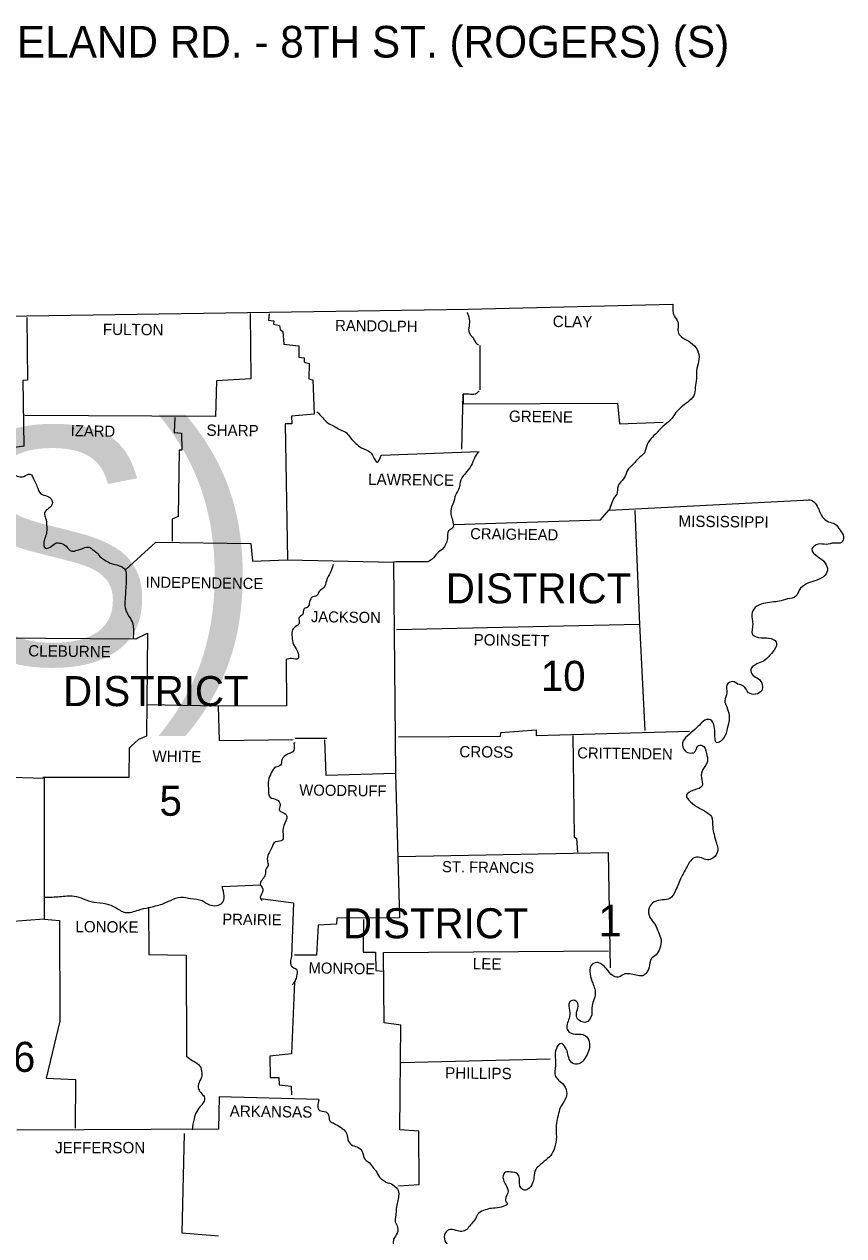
# Model space of a CAD drawing. Extents: x 309389.3 to 309420.2, y 336441.4 to 336461.2.
# Drawn here: x 309416.789 to 309419.827, y 336456.398 to 336460.893 of the extents above; entities that cross this region are included whole.
import ezdxf

# ---------------------------------------------------------------- set-up
doc = ezdxf.new("R2010")
doc.units = 0
doc.layers.add('Level 1', color=7, linetype='Continuous')
doc.layers.add('Level 63', color=7, linetype='Continuous')

msp = doc.modelspace()

# ---------------------------------------------------------------- linework, layer by layer
at = {"layer": 'Level 63'}
for p, q in [((309418.9619, 336459.1024), (309418.9736, 336459.1308)), ((309418.9589, 336459.0907), (309418.9706, 336459.1269)), ((309417.7936, 336458.2441), (309417.91, 336458.2441))]:
    msp.add_line(p, q, dxfattribs=at)
for points in [[(309413.8305, 336459.8092), (309415.4112, 336459.8082), (309416.7984, 336459.8112), (309418.4349, 336459.8366), (309419.1935, 336459.8542)], [(309416.7984, 336459.8053), (309416.8004, 336459.5726), (309416.7838, 336459.5717), (309416.7867, 336459.3282), (309416.7183, 336459.3185), (309416.7241, 336459.253), (309416.7476, 336459.2227), (309416.7457, 336459.1454), (309416.6127, 336459.1406), (309416.6078, 336459.0213), (309416.4866, 336459.0174), (309416.4807, 336458.8727), (309416.4876, 336458.861), (309416.4905, 336458.6302), (309416.6997, 336458.6166), (309416.6968, 336458.1014), (309416.863, 336458.0965), (309416.863, 336457.5725), (309416.732, 336457.5627), (309416.7222, 336457.4474), (309416.5022, 336457.4464)], [(309417.6265, 336459.82), (309417.6284, 336459.5775), (309417.5013, 336459.5707), (309417.4974, 336459.4377), (309416.7906, 336459.4416)], [(309417.6969, 336459.819), (309417.6939, 336459.7955), (309417.7135, 336459.7926), (309417.7125, 336459.7809), (309417.735, 336459.776), (309417.7369, 336459.7603), (309417.7477, 336459.7535), (309417.7506, 336459.7066), (309417.8063, 336459.7007), (309417.8063, 336459.6587), (309417.8269, 336459.6557), (309417.8269, 336459.6391), (309417.8445, 336459.6342), (309417.8435, 336459.5775), (309417.8591, 336459.5746), (309417.863, 336459.4465), (309417.7799, 336459.4387), (309417.7809, 336459.4113), (309417.7555, 336459.4104), (309417.7643, 336458.9059), (309418.1583, 336458.8971), (309418.1651, 336458.1131), (309417.908, 336458.1063), (309417.9031, 336458.2382)], [(309418.4779, 336459.7017), (309418.4779, 336459.5365)], [(309418.4115, 336459.3165), (309418.4164, 336459.5208), (309418.4164, 336459.4847), (309418.9882, 336459.4876), (309418.9961, 336459.4113), (309419.1574, 336459.4172)], [(309417.3469, 336459.4348), (309417.3449, 336459.3781), (309417.3723, 336459.3761), (309417.3733, 336459.3136), (309417.3635, 336459.3136), (309417.3596, 336459.0672), (309417.3371, 336459.0575), (309417.3371, 336458.9753)], [(309418.1123, 336459.295), (309418.475, 336459.3077)], [(309418.9589, 336459.0907), (309419.7009, 336459.1288)], [(309418.3821, 336459.0369), (309418.9247, 336459.0545), (309418.957, 336459.0917)], [(309419.0528, 336459.0897), (309419.0694, 336458.6664), (309419.0889, 336458.2725)], [(309417.165, 336458.8707), (309417.2765, 336458.9714), (309417.6284, 336458.9665), (309417.6353, 336458.901), (309417.7633, 336458.9059)], [(309418.2863, 336458.8991), (309418.1671, 336458.8991), (309418.1583, 336458.8971)], [(309416.6997, 336458.6166), (309417.2022, 336458.6136), (309417.2452, 336458.6342), (309417.2423, 336458.2519), (309417.2129, 336458.2392), (309417.1865, 336458.2167), (309417.1778, 336458.2079), (309417.1768, 336458.0984), (309416.8571, 336458.0984)], [(309419.0694, 336458.6664), (309418.169, 336458.6459)], [(309417.7594, 336458.5364), (309417.7614, 336458.3643), (309417.5072, 336458.3634), (309417.2462, 336458.3683)], [(309417.5072, 336458.3634), (309417.5111, 336458.2353), (309417.7858, 336458.2402)], [(309418.1768, 336458.25), (309418.5542, 336458.2519), (309418.5552, 336458.2656), (309418.6862, 336458.2754), (309418.6862, 336458.2549), (309419.2551, 336458.2705)], [(309418.823, 336458.2549), (309418.8279, 336457.8785), (309418.8367, 336457.8726), (309418.8397, 336457.8218)], [(309418.823, 336458.2549), (309418.8279, 336457.8785), (309418.8367, 336457.8726), (309418.8397, 336457.8218)], [(309418.823, 336458.2549), (309418.8279, 336457.8785), (309418.8367, 336457.8726), (309418.8397, 336457.8218)], [(309418.823, 336458.2549), (309418.8279, 336457.8785), (309418.8367, 336457.8726), (309418.8397, 336457.8218)], [(309418.823, 336458.2549), (309418.8279, 336457.8785), (309418.8367, 336457.8726), (309418.8397, 336457.8218)], [(309417.7936, 336458.2275), (309417.7887, 336458.2265)], [(309418.1651, 336458.1131), (309418.1798, 336457.5774), (309417.9471, 336457.5764), (309417.9461, 336457.5549), (309417.8787, 336457.551), (309417.8728, 336457.4395), (309417.7907, 336457.4395)], [(309418.1768, 336457.8052), (309418.9531, 336457.8208)], [(309418.9531, 336457.8208), (309418.9609, 336457.3926)], [(309418.9531, 336457.8208), (309418.9609, 336457.3926)], [(309418.9531, 336457.8208), (309418.9609, 336457.3926)], [(309418.9531, 336457.8208), (309418.9609, 336457.3926)], [(309418.9531, 336457.8208), (309418.9609, 336457.3926)], [(309418.9531, 336457.8208), (309418.9609, 336457.3926)], [(309418.9531, 336457.8208), (309418.9609, 336457.3926)], [(309418.9531, 336457.8208), (309418.9609, 336457.3926)], [(309417.5228, 336457.6937), (309417.6646, 336457.7006)], [(309417.6646, 336457.6497), (309417.7868, 336457.6341), (309417.7799, 336457.4347)], [(309417.2491, 336457.6175), (309417.2511, 336457.4425), (309417.3889, 336457.4395), (309417.3899, 336457.0642)], [(309416.863, 336457.5725), (309416.9197, 336457.5686), (309416.9206, 336457.1951), (309416.8698, 336456.983), (309416.9783, 336456.9781), (309416.9773, 336456.7982)], [(309418.0468, 336457.5715), (309418.0458, 336457.4503), (309418.0908, 336457.4503), (309418.0928, 336457.3828), (309418.1211, 336457.3799)], [(309418.1768, 336456.5832), (309418.2531, 336456.5881), (309418.2521, 336456.7865), (309418.1808, 336456.7914), (309418.1847, 336457.1795), (309418.1231, 336457.1883), (309418.1211, 336457.4493), (309418.955, 336457.4552)], [(309417.7907, 336457.3408), (309417.779, 336457.0729), (309417.6988, 336457.0642), (309417.7008, 336456.985), (309417.733, 336456.9859), (309417.734, 336456.9586), (309417.778, 336456.9537), (309417.779, 336456.9214)], [(309418.1866, 336457.0417), (309418.738, 336457.0554)], [(309417.8806, 336456.9038), (309417.5111, 336456.9136), (309417.5092, 336456.7934), (309416.7613, 336456.7904)], [(309417.3811, 336456.7777), (309417.3733, 336456.4092), (309417.5092, 336456.3984)]]:
    msp.add_lwpolyline(points, dxfattribs=at)
for points in [[(309419.1935, 336459.8542), (309419.1984, 336459.8112), (309419.2121, 336459.7887), (309419.2141, 336459.7476), (309419.2307, 336459.73), (309419.259, 336459.7124), (309419.2845, 336459.6841), (309419.2903, 336459.6509), (309419.2825, 336459.6166), (309419.2805, 336459.5785), (309419.2766, 336459.5453), (309419.2708, 336459.515), (309419.2473, 336459.4905), (309419.2248, 336459.4729), (309419.2043, 336459.4524), (309419.1896, 336459.4309), (309419.1642, 336459.4074), (309419.1388, 336459.383), (309419.1183, 336459.3615), (309419.0977, 336459.3341), (309419.088, 336459.3038), (309419.0655, 336459.2823), (309419.0479, 336459.2627), (309419.0244, 336459.2364), (309419.0127, 336459.21), (309418.9902, 336459.1797), (309418.9853, 336459.1503), (309418.9706, 336459.1269), (309418.9697, 336459.123)], [(309418.43, 336459.8239), (309418.4388, 336459.7994), (309418.4379, 336459.7731), (309418.4379, 336459.7486), (309418.4506, 336459.732), (309418.4633, 336459.7115), (309418.4731, 336459.7027)], [(309418.474, 336459.5335), (309418.4613, 336459.5208), (309418.4369, 336459.5208), (309418.4164, 336459.5208)], [(309417.8738, 336459.4553), (309417.8953, 336459.4329), (309417.9139, 336459.4143), (309417.9354, 336459.4035), (309417.9608, 336459.3889), (309417.9833, 336459.3771), (309417.9979, 336459.3586), (309418.0185, 336459.338), (309418.039, 336459.3214), (309418.0713, 336459.3058), (309418.082, 336459.2891), (309418.0967, 336459.2686), (309418.1123, 336459.295)], [(309418.4721, 336459.3067), (309418.4574, 336459.2833), (309418.4457, 336459.2559), (309418.4222, 336459.2246), (309418.4046, 336459.1943), (309418.4017, 336459.1738), (309418.388, 336459.1464), (309418.3802, 336459.119), (309418.3714, 336459.0956), (309418.3714, 336459.0711), (309418.3782, 336459.0467), (309418.3763, 336459.0242), (309418.3616, 336459.0135), (309418.3577, 336458.9851), (309418.3518, 336458.9656), (309418.3391, 336458.946), (309418.3206, 336458.9313), (309418.301, 336458.9089), (309418.2863, 336458.8991)], [(309416.7476, 336459.2227), (309416.7867, 336459.2158), (309416.8102, 336459.2246), (309416.8268, 336459.1992), (309416.8356, 336459.1797), (309416.8503, 336459.1513), (309416.8737, 336459.1425), (309416.8913, 336459.1269), (309416.8913, 336459.1102), (309416.8757, 336459.0946), (309416.8639, 336459.079), (309416.8679, 336459.0604), (309416.8718, 336459.035), (309416.8718, 336459.0105), (309416.8659, 336458.988), (309416.861, 336458.9675), (309416.8659, 336458.9499), (309416.8845, 336458.9529), (309416.904, 336458.9675), (309416.9246, 336458.9675), (309416.9441, 336458.9568), (309416.9646, 336458.9382), (309416.9852, 336458.9421), (309417.0018, 336458.947), (309417.0252, 336458.9538), (309417.0419, 336458.945), (309417.0565, 336458.9333), (309417.0741, 336458.9147), (309417.0907, 336458.903), (309417.1123, 336458.8922), (309417.1386, 336458.8854), (309417.1631, 336458.8688), (309417.167, 336458.8404), (309417.166, 336458.816), (309417.1641, 336458.7857), (309417.1621, 336458.7524), (309417.165, 336458.7202), (309417.1758, 336458.6987), (309417.1895, 336458.6733), (309417.1934, 336458.6498), (309417.1924, 336458.6127)], [(309419.6902, 336459.1278), (309419.7009, 336459.1288), (309419.7341, 336459.0936), (309419.7488, 336459.0643), (309419.7703, 336459.0477), (309419.7948, 336459.0389), (309419.8133, 336459.0164), (309419.826, 336458.992), (309419.8192, 336458.9705), (309419.7918, 336458.9685), (309419.7615, 336458.9636), (309419.7322, 336458.9646), (309419.7087, 336458.945), (309419.7302, 336458.9186), (309419.7586, 336458.8942), (309419.7664, 336458.8678), (309419.7508, 336458.8424), (309419.7195, 336458.8287), (309419.6892, 336458.817), (309419.6618, 336458.7935), (309419.6491, 336458.771), (309419.6188, 336458.7612), (309419.5875, 336458.7524), (309419.5601, 336458.7495), (309419.5289, 336458.7436), (309419.4985, 336458.729), (309419.4858, 336458.7036), (309419.4897, 336458.6674), (309419.4888, 336458.6293), (309419.521, 336458.6166), (309419.5494, 336458.6156), (309419.5768, 336458.6009), (309419.5738, 336458.5794), (309419.5533, 336458.552), (309419.5289, 336458.5305), (309419.5044, 336458.5198), (309419.4819, 336458.4993), (309419.4897, 336458.4787), (309419.5103, 336458.465), (309419.5249, 336458.4426), (309419.523, 336458.422), (309419.4995, 336458.4074), (309419.4741, 336458.4132), (309419.4555, 336458.4377), (309419.434, 336458.4455), (309419.4155, 336458.4543), (309419.3939, 336458.4416), (309419.3939, 336458.4132), (309419.3861, 336458.3829), (309419.393, 336458.3604), (309419.4018, 336458.3292), (309419.4008, 336458.3057), (309419.393, 336458.2725), (309419.3763, 336458.2382), (309419.3568, 336458.2275), (309419.349, 336458.2646), (309419.3451, 336458.2949), (309419.3333, 336458.3125), (309419.3177, 336458.3135), (309419.2972, 336458.2988), (309419.2747, 336458.2764), (309419.2463, 336458.2519), (309419.2297, 336458.2275), (309419.2385, 336458.1972), (309419.26, 336458.1894), (309419.2766, 336458.1952), (309419.2854, 336458.2148), (309419.3021, 336458.2177), (309419.3177, 336458.1874)], [(309417.9344, 336458.8883), (309417.9227, 336458.858), (309417.909, 336458.8287), (309417.9002, 336458.8033), (309417.8816, 336458.7886), (309417.8757, 336458.7749), (309417.8591, 336458.7691), (309417.8464, 336458.7495), (309417.8406, 336458.7319), (309417.8269, 336458.7241), (309417.82, 336458.7026), (309417.8073, 336458.6909), (309417.8083, 336458.6713), (309417.7936, 336458.6576), (309417.7819, 336458.642), (309417.7819, 336458.6205), (309417.7868, 336458.5921), (309417.7966, 336458.5755), (309417.8054, 336458.554), (309417.8044, 336458.5403), (309417.7799, 336458.5403), (309417.7594, 336458.5364)], [(309417.7887, 336458.2265), (309417.7839, 336458.1942), (309417.7653, 336458.1854), (309417.7438, 336458.1639), (309417.7389, 336458.1444), (309417.7213, 336458.1366), (309417.7047, 336458.116), (309417.6939, 336458.0877), (309417.6939, 336458.0584), (309417.7008, 336458.0251), (309417.7252, 336458.0163), (309417.7369, 336457.9968), (309417.735, 336457.9762), (309417.7584, 336457.9626), (309417.7623, 336457.9508), (309417.7584, 336457.9381), (309417.7477, 336457.9019), (309417.7487, 336457.8775), (309417.7467, 336457.8668), (309417.7203, 336457.8599), (309417.7047, 336457.8335), (309417.6939, 336457.8149), (309417.69, 336457.7905), (309417.6929, 336457.7729), (309417.6851, 336457.7592), (309417.6822, 336457.7387), (309417.6724, 336457.7211), (309417.6636, 336457.7045), (309417.6734, 336457.6849), (309417.6705, 336457.6712), (309417.6646, 336457.6497), (309417.6695, 336457.6429)], [(309419.3177, 336458.1874), (309419.3216, 336458.1591), (309419.305, 336458.1287), (309419.2991, 336458.0984), (309419.3021, 336458.0681), (309419.2708, 336458.0515), (309419.2434, 336458.032), (309419.259, 336458.0085), (309419.2884, 336457.987), (309419.3177, 336457.9704), (309419.3363, 336457.9538), (309419.3412, 336457.9137), (309419.346, 336457.8883), (309419.3558, 336457.8531), (309419.3597, 336457.8286), (309419.3421, 336457.7993), (309419.3216, 336457.7934), (309419.3001, 336457.8003), (309419.2747, 336457.8022), (309419.2542, 336457.7827), (309419.2395, 336457.7553), (309419.2248, 336457.7279), (309419.2141, 336457.7045), (309419.2033, 336457.6791), (309419.1818, 336457.6497), (309419.1554, 336457.6448), (309419.1241, 336457.637), (309419.1056, 336457.6155), (309419.1085, 336457.5793), (309419.1261, 336457.5549), (309419.1398, 336457.5246), (309419.1495, 336457.4982), (309419.1447, 336457.465), (309419.131, 336457.4405), (309419.1134, 336457.4259), (309419.1056, 336457.3946), (309419.0928, 336457.3711), (309419.0811, 336457.3633), (309419.0577, 336457.3652), (309419.0322, 336457.3701), (309419.0107, 336457.3682), (309418.9902, 336457.3574), (309418.9697, 336457.3643), (309418.9482, 336457.3877), (309418.9306, 336457.4053), (309418.911, 336457.4122), (309418.8905, 336457.4014), (309418.8866, 336457.3692), (309418.8964, 336457.3359), (309418.9052, 336457.291), (309418.8964, 336457.2636), (309418.8934, 336457.2186)], [(309416.8649, 336457.6546), (309416.9197, 336457.6566), (309416.9734, 336457.6585), (309417.0076, 336457.6487), (309417.0468, 336457.636), (309417.0927, 336457.6302), (309417.125, 336457.6175), (309417.1631, 336457.5979), (309417.212, 336457.6067), (309417.2501, 336457.6165), (309417.2999, 336457.6292), (309417.3322, 336457.6429), (309417.3694, 336457.6546), (309417.4065, 336457.6497), (309417.4485, 336457.6419), (309417.4749, 336457.6263), (309417.5228, 336457.6331), (309417.5228, 336457.6937)], [(309417.7799, 336457.4347), (309417.776, 336457.4151), (309417.7839, 336457.3946), (309417.7975, 336457.3877), (309417.7995, 336457.3682), (309417.7946, 336457.3486), (309417.7907, 336457.3408), (309417.7819, 336457.3291)], [(309418.8934, 336457.2186), (309418.8709, 336457.1903), (309418.8377, 336457.2079), (309418.8377, 336457.2313), (309418.8426, 336457.2558), (309418.8309, 336457.2714), (309418.8103, 336457.2646), (309418.8103, 336457.2343), (309418.8084, 336457.2049), (309418.8025, 336457.1629), (309418.8162, 336457.1502), (309418.8475, 336457.1463), (309418.87, 336457.1404), (309418.8836, 336457.1179), (309418.8827, 336457.0905), (309418.8719, 336457.0642), (309418.8563, 336457.0426), (309418.8318, 336457.0348), (309418.8123, 336457.0475), (309418.8045, 336457.0729), (309418.7957, 336457.0954), (309418.779, 336457.1121), (309418.7614, 336457.0935), (309418.7575, 336457.0593), (309418.7585, 336457.0299), (309418.7585, 336456.9899), (309418.7839, 336456.9635), (309418.7996, 336456.9332), (309418.7947, 336456.9058), (309418.7761, 336456.8735), (309418.7683, 336456.8452), (309418.7605, 336456.807), (309418.7614, 336456.765), (309418.7546, 336456.7239), (309418.7409, 336456.6966), (309418.7155, 336456.6741), (309418.6989, 336456.6594), (309418.6852, 336456.6448), (309418.6784, 336456.6154), (309418.6735, 336456.5949), (309418.6549, 336456.5705), (309418.6402, 336456.5685), (309418.6285, 336456.5783), (309418.6246, 336456.5949), (309418.6246, 336456.6115), (309418.6168, 336456.6281), (309418.5923, 336456.635), (309418.5728, 336456.634), (309418.564, 336456.6203), (309418.5767, 336456.5822), (309418.5816, 336456.5578), (309418.5747, 336456.5245), (309418.5786, 336456.5206), (309418.5434, 336456.502), (309418.5151, 336456.4991), (309418.4916, 336456.4923), (309418.4691, 336456.4776), (309418.4584, 336456.4561), (309418.4428, 336456.4385), (309418.4291, 336456.4219), (309418.4105, 336456.4141), (309418.39, 336456.418), (309418.3626, 336456.4209), (309418.3469, 336456.4013), (309418.3518, 336456.373), (309418.3704, 336456.3564), (309418.3978, 336456.3486), (309418.4261, 336456.3505), (309418.4535, 336456.3534), (309418.4789, 336456.3398), (309418.474, 336456.3134), (309418.4496, 336456.3007), (309418.4134, 336456.2967), (309418.3841, 336456.2997), (309418.3489, 336456.2919), (309418.3313, 336456.2694), (309418.3411, 336456.2352), (309418.3792, 336456.2215), (309418.3968, 336456.1892), (309418.3978, 336456.1589), (309418.3851, 336456.1188), (309418.3675, 336456.1002), (309418.3333, 336456.0924), (309418.3069, 336456.0875), (309418.303, 336456.0426), (309418.2912, 336456.0201), (309418.2707, 336456.0132), (309418.2414, 336456.0279), (309418.2238, 336456.0347), (309418.2023, 336456.0445), (309418.1749, 336456.0611), (309418.1544, 336456.0582), (309418.1602, 336456.0152), (309418.1622, 336456.0132), (309418.1856, 336455.981), (309418.2091, 336455.9556), (309418.2199, 336455.9253)], [(309417.3899, 336457.0642), (309417.4143, 336457.0475), (309417.4397, 336457.028), (309417.4466, 336457.0016), (309417.4446, 336456.983), (309417.4368, 336456.9674), (309417.4349, 336456.9429), (309417.4466, 336456.9253), (309417.4573, 336456.9107), (309417.4466, 336456.8843), (309417.428, 336456.8598), (309417.4182, 336456.8325), (309417.4114, 336456.7914)], [(309417.8806, 336456.9038), (309417.8836, 336456.8637), (309417.907, 336456.8579), (309417.9168, 336456.8471), (309417.9217, 336456.8246), (309417.9383, 336456.8149), (309417.9608, 336456.8012), (309417.9745, 336456.7914), (309417.9843, 336456.7758), (309417.9901, 336456.7503), (309418.0058, 336456.7337), (309418.0273, 336456.7259), (309418.0429, 336456.7073), (309418.0527, 336456.6809), (309418.0683, 336456.6692), (309418.084, 336456.6487), (309418.0918, 336456.6399), (309418.1055, 336456.6164), (309418.1192, 336456.6047), (309418.1289, 336456.5978), (309418.1446, 336456.593), (309418.1641, 336456.5802), (309418.1768, 336456.5607), (309418.1768, 336456.546), (309418.172, 336456.5235), (309418.168, 336456.5001), (309418.1661, 336456.4737), (309418.1641, 336456.4502), (309418.1729, 336456.4307), (309418.168, 336456.4013), (309418.1583, 336456.3857), (309418.1573, 336456.3642), (309418.1544, 336456.3319), (309418.1505, 336456.3134), (309418.1417, 336456.2831), (309418.1289, 336456.2674)]]:
    msp.add_spline(points, degree=3, dxfattribs=at)

# ---------------------------------------------------------------- texts
at = {"layer": 'Level 1'}
for s, height, p in [('DIXIELAND RD. - 8TH ST. (ROGERS) (S)', 0.117311, (309416.4565, 336460.7698)), ('DIXIELAND RD. - 8TH ST.  (ROGERS) (S)', 0.879831, (309395.2502, 336458.5178))]:
    msp.add_text(s, height=height, dxfattribs=at).set_placement(p)
at = {"layer": 'Level 63'}
for s, height, rotation, p in [('CLAY', 0.04203, 359.2258, (309418.7478, 336459.7701)), ('FULTON', 0.04203, 359.4996, (309417.08, 336459.7408)), ('RANDOLPH', 0.04106, 359.2583, (309417.9412, 336459.7555)), ('GREENE', 0.04204, 359.2361, (309418.5855, 336459.4182)), ('IZARD', 0.04105, 358.9258, (309416.9607, 336459.3654)), ('SHARP', 0.04203, 359.3905, (309417.4642, 336459.3664)), ('LAWRENCE', 0.04204, 359.2678, (309418.0634, 336459.1845)), ('MISSISSIPPI', 0.042031, 359.3097, (309419.2141, 336459.0291)), ('CRAIGHEAD', 0.04106, 359.1159, (309418.4418, 336458.9832)), ('INDEPENDENCE', 0.041052, 359.2187, (309417.2384, 336458.8033)), ('JACKSON', 0.04105, 359.1352, (309417.8513, 336458.6752)), ('CLEBURNE', 0.04203, 359.2535, (309416.8033, 336458.5481)), ('POINSETT', 0.04203, 359.1987, (309418.4545, 336458.5892)), ('WHITE', 0.04204, 359.3139, (309417.2638, 336458.1571)), ('CROSS', 0.04203, 359.3839, (309418.4017, 336458.1737)), ('CRITTENDEN', 0.04106, 359.213, (309418.8387, 336458.1698)), ('WOODRUFF', 0.04105, 359.2748, (309417.8083, 336458.032)), ('ST. FRANCIS', 0.041052, 359.2216, (309418.3372, 336457.7475)), ('LONOKE', 0.04204, 359.4974, (309416.9783, 336457.5246)), ('PRAIRIE', 0.04106, 359.2116, (309417.5228, 336457.5529)), ('LEE', 0.04204, 359.4327, (309418.4515, 336457.3868)), ('MONROE', 0.04105, 359.0331, (309417.8425, 336457.3721)), ('PHILLIPS', 0.04203, 359.3179, (309418.3489, 336456.982)), ('ARKANSAS', 0.04203, 359.2678, (309417.5502, 336456.8403))]:
    msp.add_text(s, height=height, rotation=rotation, dxfattribs=at).set_placement(p)
for s, height, p in [('DISTRICT', 0.11144, (309418.3518, 336458.7446)), ('10', 0.11145, (309418.704, 336458.4201)), ('DISTRICT', 0.11144, (309416.9329, 336458.3635)), ('5', 0.1114, (309417.2902, 336457.9567)), ('DISTRICT', 0.11144, (309417.9706, 336457.5021)), ('1', 0.1173, (309418.9169, 336457.509)), ('DISTRICT 6', 0.11144, (309416.0183, 336457.0065)), ('JEFFERSON', 0.04204, (309416.903, 336456.7044))]:
    msp.add_text(s, height=height, dxfattribs=at).set_placement(p)

doc.saveas('drawing.dxf')
